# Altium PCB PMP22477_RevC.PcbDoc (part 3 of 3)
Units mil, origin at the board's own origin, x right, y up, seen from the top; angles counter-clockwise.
Board outline 5000 x 3000 mil, 4 copper layers (Top Layer, Signal Layer 1, Signal Layer 2, Bottom Layer), stack 61.2 mil thick; 191 components, 134 nets, 569 pads, 237 vias.
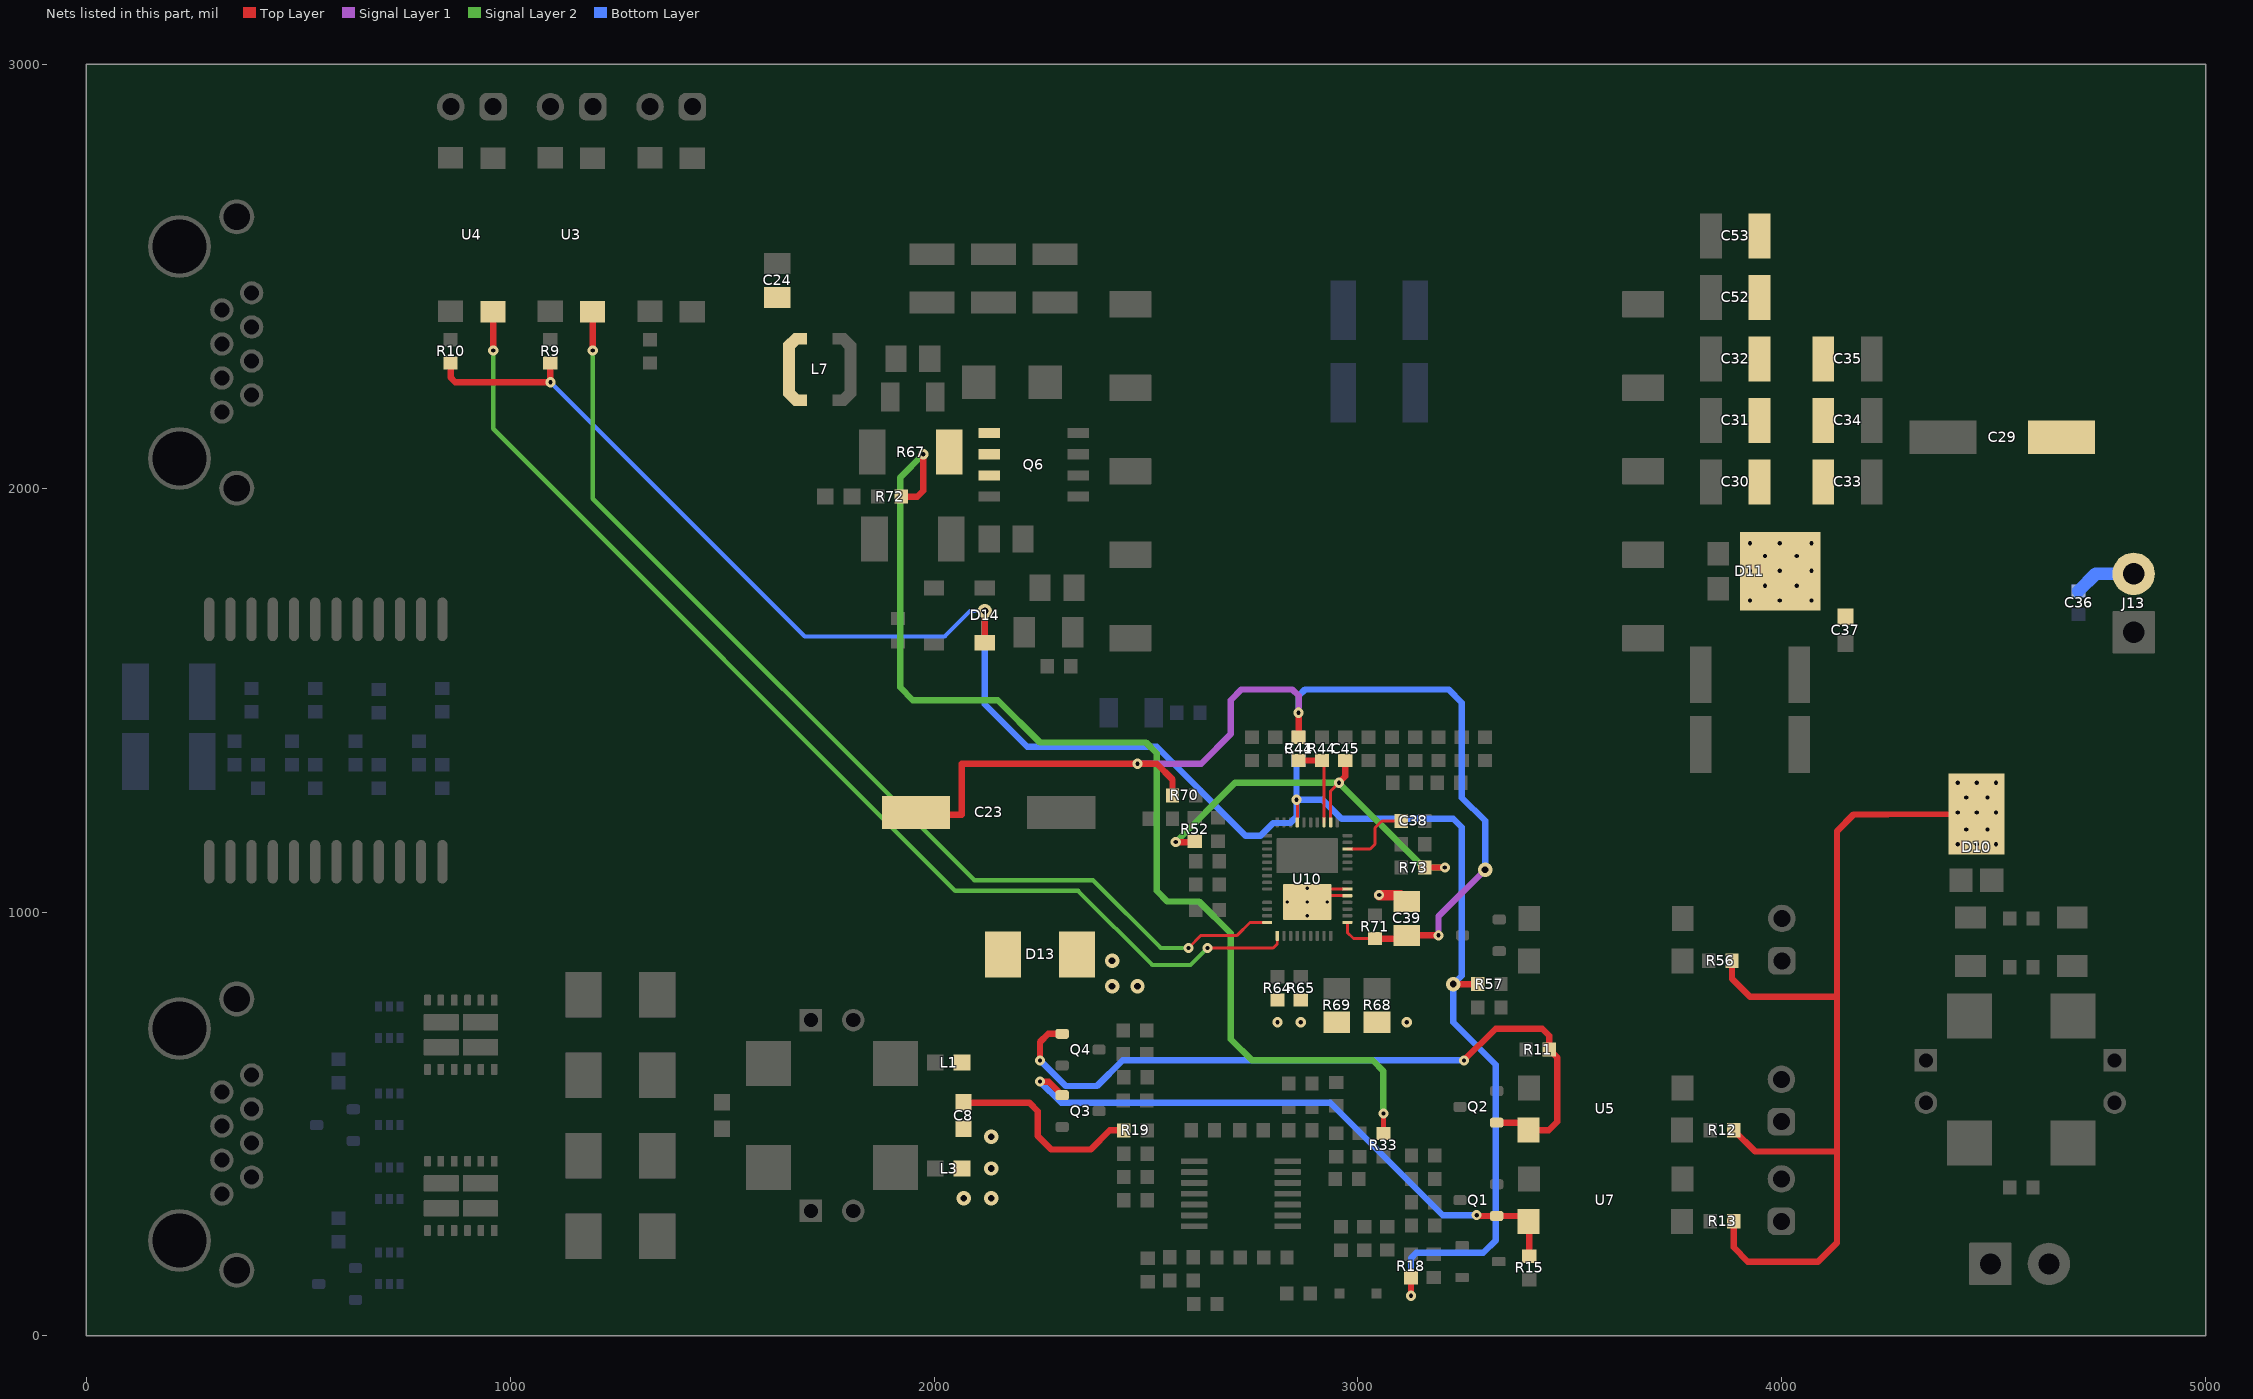
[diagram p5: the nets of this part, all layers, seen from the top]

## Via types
v1: diameter 34, hole 16, Top Layer to Bottom Layer, 127 vias
v2: diameter 24, hole 10, Top Layer to Bottom Layer, 97 vias
v3: diameter 19.68, hole 7.87, Top Layer to Bottom Layer, 13 vias

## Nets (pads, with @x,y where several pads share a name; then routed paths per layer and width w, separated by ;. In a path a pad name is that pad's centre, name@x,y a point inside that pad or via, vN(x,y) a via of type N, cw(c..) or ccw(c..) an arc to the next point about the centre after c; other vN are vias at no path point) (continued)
RSEN: Q6.1 Q6.2 Q6.3 R33.2 R67.1 R72.2 | length 2715.7
  Top Layer w12: R33.2@3060,477.56 v2(3060,525)
  Top Layer w15: R72.2@1922.56,1980 1960.59,1980 1974.69,1994.09 v2(1974.69,2080)
  Signal Layer 2 w15: v2(1974.69,2080) 1920,2025.31 1920,1530 1950,1500 2150,1500 2250,1400 2500,1400 2525,1375 2525,1050 2550,1025 2625,1025 2700,950 2700,700 2750,650 3035,650 3060,625 v2(3060,525)
SS: C38.1 U10.33 | length 177.6
  Top Layer w7: U10.33@2975,1148.74 3028.74,1148.74 3040,1160 3040,1198.7 3056.3,1215 C38.1@3102.44,1215
TPH: U3.2 U10.13 | length 2497.3
  Top Layer w7: v2(2600,915) 2630,945 2715,945 2745.51,975.51 U10.13@2786.02,975.51
  Top Layer w10: v2@1194.54,2325.46 v2(1195,2325)
  Top Layer w15: U3.2@1194.54,2416.32 1195,2415.86 v2(1195,2325)
  Signal Layer 2 w10: v2(1195,2325) 1195,1975 2095,1075 2375,1075 2535,915 v2(2600,915)
TPL: U4.2 U10.14 | length 2690.7
  Top Layer w7: v2(2645,915) 2800,915 2809.65,924.65 U10.14@2809.65,944.02
  Top Layer w10: v2@959.54,2325.46 v2(960,2325)
  Top Layer w15: U4.2@959.54,2416.32 960,2415.86 v2(960,2325)
  Signal Layer 2 w10: v2(960,2325) 960,2140 2050,1050 2340,1050 2515,875 2605,875 v2(2645,915)
TYPE1: Q2.1 Q4.1 R11.2 U5.4 | length 1762.7
  Top Layer w15: v2(2250,650) 2250,693.5 2269.36,712.86 Q4.1@2302.36,712.86 ; v2(3250,650) 3325,725 3435,725 3451.54,708.46 R11.2@3451.54,675.46 3470,656.99 3470,505 3450.46,485.46 U5.4@3402.38,485.46 3384.78,503.06 Q2.1@3327.28,503.06
  Bottom Layer w15: v2(2250,650) 2310.49,589.51 2384.51,589.51 2445,650 v2(3250,650)
TYPE2: Q1.1 Q3.1 R15.2 U7.4 | length 1437.7
  Top Layer w15: v2(2250,600) 2270.22,600 Q3.1@2302.36,567.86 ; v2(3280,285) 3281.94,283.06 Q1.1@3327.28,283.06 3389.78,283.06 U7.4@3402.38,270.46 3403.98,268.86 R15.2@3403.98,188.02
  Bottom Layer w15: v2(2250,600) 2300,550 2935,550 3200,285 v2(3280,285)
UV: R41.1 R44.2 U10.38 | length 202.7
  Top Layer w7: R44.2@2915,1357.44 2919.88,1352.56 U10.38@2919.88,1211.73
  Top Layer w15: R41.1@2860,1357.44 R44.2@2915,1357.44
VB: C45.1 R52.1 R73.1 U10.37 | length 1029.2
  Top Layer w7: U10.37@2935.63,1211.73 2935.63,1285.63 v2(2955,1305)
  Top Layer w15: v2(2570,1165) 2612.56,1165 R52.1@2615,1167.44 ; v2(2955,1305) 2970,1320 C45.1@2970,1357.44 ; R73.1@3157.56,1105 v2(3205,1105)
  Signal Layer 2 w15: v2(2570,1165) 2710,1305 v2(2955,1305) 3155,1105 v2(3205,1105)
VCC: C44.1 D14.1 R9.2 R10.2 R18.2 R57.1 U10.42 | length 4831.3
  Top Layer w7: v2(2855,1265) 2856.89,1263.11 U10.42@2856.89,1211.73
  Top Layer w15: R10.2@859.54,2295.35 859.54,2261.13 870.67,2250 v2(1095,2250) 1094.54,2250.46 R9.2@1094.54,2295.35 ; D14.1@2120,1635.53 v1(2120,1710) ; R18.2@3123.98,137.9 3125,136.87 v2(3125,95) ; v1(3225,830) R57.1@3282.44,830
  Bottom Layer w10: v2(1095,2250) 1695,1650 2025,1650 2085,1710 v1(2120,1710)
  Bottom Layer w15: v1(2120,1710) 2120,1490 2220,1390 2525,1390 2734.76,1180.24 2770.24,1180.24 2800,1210 2840,1210 2855,1225 v2(2855,1265) ; C44.1@2860,1357.44 2855,1352.44 v2(2855,1265) ; v2(3125,95) 3125,183.7 3137.31,196.01 3296.01,196.01 3325,225 3325,640 3225,740 v1(3225,830) 3245,850 3245,1200 3225,1220 2961.34,1220 2916.34,1265 v2(2855,1265)
VDD: C8.1 C23.1 C24.1 C39.1 D13.1 L1.2 L7.1 R19.2 R41.2 R70.2 R71.1 U10.23 | length 3169.4
  Top Layer w7: U10.23@2975,975.51 2975,951.81 2989.37,937.44 R71.1@3040,937.44
  Top Layer w15: C23.1@1957.48,1235 1962.6,1229.88 2065,1229.88 2065,1350 v2(2480,1350) 2525,1350 2562.44,1312.56 R70.2@2562.44,1275 ; C8.1@2069.43,551.5 2070.93,550 2225,550 2245,530 2245,471.65 2276.65,440 2369.88,440 2414.88,485 R19.2@2447.44,485 ; R41.2@2860,1412.56 v2(2860,1470) ; R71.1@3040,937.44 3107.44,937.44 C39.1@3115,945 v2(3190,945)
  Signal Layer 1 w15: v2(2480,1350) 2630,1350 2700,1420 2700,1500 2725,1525 2845,1525 2860,1510 v2(2860,1470) ; v2(3190,945) 3190,990 v1(3300,1100)
  Bottom Layer w15: v2(2860,1470) 2860,1510 2875,1525 3213.85,1525 3245,1493.85 3245,1270 3300,1215 v1(3300,1100)
VOUT: C29.1 C30.2 C31.2 C32.2 C33.2 C34.2 C35.2 C36.1 C37.1 C52.2 C53.2 D10.3 D11.3 J13.2 R12.1 R13.1 R56.1 | length 2372
  Top Layer w15: R56.1@3882.56,885 3882.56,842.44 3925,800 4130,800 ; R13.1@3886.54,270.46 3886.54,208.92 3920,175.46 4085.46,175.46 4130,220 4130,435 ; R12.1@3886.54,485.46 3936.99,435 4130,435 ; D10.3@4458.78,1231.77 4415.03,1231.4 4250,1230 4168.98,1230 4130,1191.02 4130,800 ; 4130,435 4130,800
  Bottom Layer w30: C36.1@4700,1757.56 4740.44,1798 J13.2@4830,1798
  other v2: 4415,1160 4460,1160 4505,1160 4435,1195 4485,1195 4415,1235 4460,1235 4505,1235 4435,1270 4485,1270 4415,1305 4460,1305 4505,1305 3925,1735 3995,1735 4070,1735 3960,1770 4035,1770 3925,1805 3995,1805 4070,1805 3960,1840 4035,1840 3925,1870 3995,1870 4070,1870
VSS: C8.2 C39.2 D13.2 L3.2 R64.1 R65.1 R68.1 R69.1 U10.27 U10.28 U10.47 | length 258.1
  Top Layer w7: v3(2880.51,1023.74) U10.47@2895.28,1038.5 ; U10.27@2975,1038.5 U10.47@2895.28,1038.5 ; U10.28@2975,1054.25 2911.02,1054.25 U10.47@2895.28,1038.5
  Top Layer w25: v2(3050,1040) 3100,1040 C39.2@3115,1025
  other v1: 2070,325 2135,325 2135,395 2135,470 2420,825 2480,825 2420,885
  other v2: 2810,740 2865,740 3115,740
  other v3: 2880.51,991.26 2833.27,1023.74 2927.76,1023.74 2880.51,1056.22
pads on no net: D17.3 D18.3 T2.2 T2.8 U9.3 U10.6 U10.10 U10.15 U10.16 U10.22 U10.25 U10.26 U10.29 U10.30 U10.41

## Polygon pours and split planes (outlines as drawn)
PGND on Top Layer "TOP_LAYER_PGND_P102" (solid, remove dead copper, pour order 102): 800,2650 2995,2650 2995,1550 3350,1550 3350,1100 3550,1100 3550,50 2045,50 2045,850 1550,850 1550,1400 800,2150
no net on Top Layer "TOP_LAYER_NONET_P086" (solid, remove dead copper, pour order 86): 2817.52,694.16
VSS on Top Layer "TOP_LAYER_VSS_P084" (solid, remove dead copper, pour order 84): 2600,700 2600,750 2550,800 2295,800 2295,1000 2450,1000 2582.76,867.24 2631.34,867.24 2631.34,868.66 2630,870 2765,870 2765,810 2885,810 2885,765 3150,765 3150,700
GND on Top Layer "TOP_LAYER_GND_P088" (solid, remove dead copper, pour order 88): 3650,50 3650,1200 3450,1200 3450,1650 3100,1650 3100,2750 800,2750 800,2950 4950,2950 4950,960 4250,960 4250,50
VSS on Top Layer "TOP_LAYER_VSS_P060" (solid, remove dead copper, pour order 60): 2200,250 2200,505 2045,505 2045,250
NetJ4_2 on Top Layer "TOP_LAYER_NETJ4_2_P056" (solid, remove dead copper, pour order 56): 1780,265 2020,265 2020,455 1855,455 1855,325 1780,325
NetJ3_2 on Top Layer "TOP_LAYER_NETJ3_2_P054" (solid, remove dead copper, pour order 54): 1780,775 2020,775 2020,585 1855,585 1855,715 1780,715
NetC15_1 on Top Layer "TOP_LAYER_NETC15_1_P052" (solid, remove dead copper, pour order 52): 4300,1105 4550,1105 4550,960 4300,960
NetC19_1 on Top Layer "TOP_LAYER_NETC19_1_P050" (solid, remove dead copper, pour order 50): 4825,620 4825,900 4575,900 4575,810 4630,810 4630,700 4740,700 4740,620
NetC19_2 on Top Layer "TOP_LAYER_NETC19_2_P048" (solid, remove dead copper, pour order 48): 4550,900 4550,810 4500,810 4500,700 4390,700 4390,620 4300,620 4300,900
NetC20_1 on Top Layer "TOP_LAYER_NETC20_1_P044" (solid, remove dead copper, pour order 44): 4575,100 4575,400 4630,400 4630,510 4740,510 4740,580 4825,580 4825,100
NetC20_2 on Top Layer "TOP_LAYER_NETC20_2_P042" (solid, remove dead copper, pour order 42): 4550,100 4550,400 4500,400 4500,510 4390,510 4390,580 4300,580 4300,100
NetD11_1 on Top Layer "TOP_LAYER_NETD11_1_P040" (solid, remove dead copper, pour order 40): 3875,1900 3875,1315 3615,1315 3615,1900
NetC37_2 on Top Layer "TOP_LAYER_NETC37_2_P038" (solid, remove dead copper, pour order 38): 4170,1645 4170,1315 3900,1315 3900,1645
VOUT on Top Layer "TOP_LAYER_VOUT_P036" (solid, remove dead copper, pour order 36): 4550,1900 4300,1900 4300,1135 4725,1135 4725,1740 4950,1740 4950,2700 3900,2700 3900,1675 4250,1675 4250,1900 4140,1900 4140,2400 4550,2400
RSEN on Top Layer "TOP_LAYER_RSEN_P034" (solid, remove dead copper, pour order 34): 2155,2145 2155,2020 1950,2020 1950,2145
VDD on Top Layer "TOP_LAYER_VDD_P032" (solid, remove dead copper, pour order 32): 2100,1390 2025,1465 1844.3,1464.3 1700,1608.61 1700,2475 1500,2475 1500,1450.31 1550,1400.31 1550,850 2045,850 2045,535 2200,535 2200,750 2250,800 2250,1100 2100,1100
NetC22_2 on Top Layer "TOP_LAYER_NETC22_2_P030" (solid, remove dead copper, pour order 30): 2065,2365 2065,2340 2415,2340 2415,2300 2625,2300 2625,2475 1760,2475 1760,2175 1935,2175 1935,2365
NetC49_2 on Top Layer "TOP_LAYER_NETC49_2_P028" (solid, remove dead copper, pour order 28): 2520,1925 2380,1925 2380,1830 2185,1830 2185,1950 2185,2160 2185,2315 2380,2315 2380,2150 2520,2150
BSP on Top Layer "TOP_LAYER_BSP_P104" (solid, remove dead copper, pour order 104): 700,2940 700,2600 400,2600 400,250 450,250 450,60 60,60 60,2940
NetC7_2 on Top Layer "TOP_LAYER_NETC7_2_P024" (solid, remove dead copper, pour order 24): 1530,505 1530,455 1665,455 1665,325 1740,325 1740,265 1470,265 1470,505
NetC7_1 on Top Layer "TOP_LAYER_NETC7_1_P022" (solid, remove dead copper, pour order 22): 1530,535 1530,585 1665,585 1665,715 1740,715 1740,775 1305,775 1305,535
NetC7_1 on Top Layer "TOP_LAYER_NETC7_1_P020" (solid, remove dead copper, pour order 20): 1425,155 1425,1050 1280,1050 1280,155
PR12 on Top Layer "TOP_LAYER_PR12_P006" (solid, remove dead copper, pour order 6): 1050,725 1050,885 1235,885 1235,725
PR36 on Top Layer "TOP_LAYER_PR36_P004" (solid, remove dead copper, pour order 4): 1235,535 1235,695 1050,695 1050,535
PR45 on Top Layer "TOP_LAYER_PR45_P002" (solid, remove dead copper, pour order 2): 1235,345 1235,505 1050,505 1050,345
PR78 on Top Layer "TOP_LAYER_PR78_P000" (solid, remove dead copper, pour order 0): 1235,155 1235,315 1050,315 1050,155
PGND on Bottom Layer "BOTTOM_LAYER_PGND_P100" (solid, remove dead copper, pour order 100): 2045,50 2045,850 1550,850 1550,1400 800,2150 800,2650 2995,2650 2995,1550 3350,1550 3350,1100 3550,1100 3550,50
GND on Bottom Layer "BOTTOM_LAYER_GND_P094" (solid, remove dead copper, pour order 94): 4250,50 4250,960 4950,960 4950,2950 800,2950 800,2750 3100,2750 3100,1650 3450,1650 3450,1200 3650,1200 3650,50
NetC37_2 on Bottom Layer "BOTTOM_LAYER_NETC37_2_P078" (solid, remove dead copper, pour order 78): 4170,1315 3900,1315 3900,1645 4170,1645
NetD11_1 on Bottom Layer "BOTTOM_LAYER_NETD11_1_P072" (solid, remove dead copper, pour order 72): 3615,1315 3615,1900 3875,1900 3875,1315
NetC22_2 on Bottom Layer "BOTTOM_LAYER_NETC22_2_P062" (solid, remove dead copper, pour order 62): 2995,2490 2995,2350 2550,2350 2550,2490
VSS on Bottom Layer "BOTTOM_LAYER_VSS_P026" (solid, remove dead copper, pour order 26): 2200,700 2650,700 3150,700 3150,1065 2825,1065 2825,870 2580,870 2500,950 2450,1000 2045,1000 2045,250 2200,250
BSP on Bottom Layer "BOTTOM_LAYER_BSP_P106" (solid, remove dead copper, pour order 106): 700,2940 700,2600 400,2600 400,250 450,250 450,60 60,60 60,2940
NetC7_2 on Bottom Layer "BOTTOM_LAYER_NETC7_2_P016" (solid, remove dead copper, pour order 16): 1280,50 1425,50 1425,265 1530,265 1530,505 1425,505 1425,885 1280,885
PR78 on Bottom Layer "BOTTOM_LAYER_PR78_P014" (solid, remove dead copper, pour order 14): 1050,155 1233.5,155 1235,156.5 1235,315 1050,315
PR45 on Bottom Layer "BOTTOM_LAYER_PR45_P012" (solid, remove dead copper, pour order 12): 1050,345 1235,345 1235,505 1050,505
PR36 on Bottom Layer "BOTTOM_LAYER_PR36_P010" (solid, remove dead copper, pour order 10): 1050,695 1235,695 1235,535 1050,535
PR12 on Bottom Layer "BOTTOM_LAYER_PR12_P008" (solid, remove dead copper, pour order 8): 1050,885 1235,885 1235,725 1050,725
NetC7_2 on Signal Layer 2 "SIGNAL_LAYER_2_NETC7_2_P108" (solid, remove dead copper, pour order 108): 890,900 890,50 1425,50 1425,150 975,150 975,900
PGND on Signal Layer 2 "SIGNAL_LAYER_2_PGND_P098" (solid, remove dead copper, pour order 98): 2045,50 3550,50 3550,1100 3350,1100 3350,1550 2995,1550 2995,2650 800,2650 800,2150 1550,1400 1550,850 2045,850
VSS on Signal Layer 2 "SIGNAL_LAYER_2_VSS_P082" (solid, remove dead copper, pour order 82): 2775,700 3150,700 3150,1065 2825,1065 2825,870 2775,870
GND on Signal Layer 2 "SIGNAL_LAYER_2_GND_P092" (solid, remove dead copper, pour order 92): 4250,50 4250,960 4950,960 4950,2950 800,2950 800,2750 3100,2750 3100,1650 3450,1650 3450,1200 3650,1200 3650,50
NetC37_2 on Signal Layer 2 "SIGNAL_LAYER_2_NETC37_2_P076" (solid, remove dead copper, pour order 76): 3900,1315 3900,1645 4170,1645 4170,1315
NetD11_1 on Signal Layer 2 "SIGNAL_LAYER_2_NETD11_1_P068" (solid, remove dead copper, pour order 68): 3615,1315 3615,1900 3875,1900 3875,1315
VOUT on Signal Layer 2 "SIGNAL_LAYER_2_VOUT_P064" (solid, remove dead copper, pour order 64): 4550,1900 4300,1900 4300,1135 4725,1135 4725,1740 4950,1740 4950,2700 3900,2700 3900,1675 4250,1675 4250,1900 4140,1900 4140,2400 4550,2400
NetC7_1 on Signal Layer 2 "SIGNAL_LAYER_2_NETC7_1_P018" (solid, remove dead copper, pour order 18): 1425,885 1290,885 1290,950 865,950 865,155 780,155 780,1050 1425,1050
PGND on Signal Layer 1 "SIGNAL_LAYER_1_PGND_P096" (solid, remove dead copper, pour order 96): 2995,2650 800,2650 800,2150 1550,1400 1550,850 2045,850 2045,50 3550,50 3550,1100 3350,1100 3350,1550 2995,1550
VSS on Signal Layer 1 "SIGNAL_LAYER_1_VSS_P080" (solid, remove dead copper, pour order 80): 3150,1065 2825,1065 2825,870 2775,870 2775,700 3150,700
GND on Signal Layer 1 "SIGNAL_LAYER_1_GND_P090" (solid, remove dead copper, pour order 90): 4250,50 4250,960 4950,960 4950,2950 800,2950 800,2750 3100,2750 3100,1650 3450,1650 3450,1200 3650,1200 3650,50
NetC37_2 on Signal Layer 1 "SIGNAL_LAYER_1_NETC37_2_P074" (solid, remove dead copper, pour order 74): 4170,1315 3900,1315 3900,1645 4170,1645
NetD11_1 on Signal Layer 1 "SIGNAL_LAYER_1_NETD11_1_P066" (solid, remove dead copper, pour order 66): 3615,1315 3875,1315 3875,1900 3615,1900

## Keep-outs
Keep-Out Layer:
  text ".Layer_Name" at 577,-858.49 h60

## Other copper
Top Layer:
  text ".Layer_Name" at 577,-858.49 h60
Bottom Layer:
  text ".Layer_Name" at 577,-858.49 h60

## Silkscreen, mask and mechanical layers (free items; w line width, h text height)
Top Overlay:
  text "'.PRJ_Number'.PCB_Rev" at 4265,2725 h108.27
  text ".Layer_Name" at 577,-858.49 h60
Bottom Overlay:
  text ".Layer_Name" at 577,-858.49 h60
Top Paste:
  text ".Layer_Name" at 577,-858.49 h60
Bottom Paste:
  text ".Layer_Name" at 577,-858.49 h60
Top Solder:
  text ".Layer_Name" at 577,-858.49 h60
  text ".Layer_Name" at 577,-858.49 h60
Bottom Solder:
  text ".Layer_Name" at 577,-858.49 h60
Drill Guide:
  text ".Layer_Name" at 577,-858.49 h60
M1 Board Outline:
  the board outline again, w10
  text ".Layer_Name" at 577,-858.49 h60
M2 Board Dimensions:
  rectangle: 0,-275 125,-150
  rectangle: 125,-400 500,-275
  lines w7: 0,-275 1000,-275 ; 125,-400 125,-150 ; 250,-400 250,-150 ; 500,-400 500,-150 ; 750,-400 750,-150 ; 0,-400 1000,-400 1000,-150 0,-150 0,-400
  text ".Layer_Name" at 577,-858.49 h60
M3 3D STEP Top:
  text ".Layer_Name" at 577,-858.49 h60
M4 3D STEP Bottom:
  text ".Layer_Name" at 577,-858.49 h60
M5 Assembly Top:
  lines w10: -292,-930.17 6308,-930.17 ; -292,-726.83 6310,-726.83 ; -292,-523.5 -292,-1133.5 3713,-1133.5 6310,-1133.5 6310,-523.5 -291.5,-523.5 -291.5,-1133.5 1284,-1133.5 ; 2173,-1133.5 2173,-523.5 ; 3440,-726.83 3440,-523.5 ; 4280,-726.83 4280,-523.5 ; 4902,-1140 4902,-937.17
  text "COMPONENTS MARKED 'DNP' SHOULD NOT BE POPULATED." at 1153.5,-318.5 h60
  text "ASSEMBLY VARIANT:" at 1153,-434 h60
  text ".VariantName" at 2189,-434 h60
  text "PCB VIEWED FROM TOP SIDE" at -228.5,-655.67 h60
  text "BOARD #:" at 2248,-655.67 h60
  text ".PRJ_Number" at 2793.5,-655.67 h60
  text "REV:" at 3638,-655.67 h60
  text ".PCB_Rev" at 3929.5,-655.67 h60
  text "SVN REV:" at 4476,-655.67 h60
  text ".VersionControl_RevNumber" at 4982,-655.67 h60
  text "TID #:" at 2248,-859 h60
  text ".TID" at 2793.5,-859 h60
  text "PLOT NAME =" at -228.5,-1064.34 h60
  text ".plot_File_Name" at 577,-1064.34 h60
  text "GENERATED    :" at 2250,-1064.34 h60
  text ".Print_Date" at 3119.5,-1064.34 h60
  text ".Print_Time" at 3848.5,-1064.34 h60
  text "TEXAS INSTRUMENTS" at 5113,-1064.34 h60
M6 Assembly Bottom:
  lines w10: -292.5,-727.33 6309.5,-727.33 ; -290.5,-930.67 6309.5,-930.67 ; 1115.5,-1140.5 1115.5,-937.67 ; 1737.5,-727.33 1737.5,-524 ; 2577.5,-727.33 2577.5,-524 ; 3844.5,-1134 3844.5,-524 ; 4733.5,-1134 6309,-1134 6309,-524 -292.5,-524 -292.5,-1134 2304.5,-1134 6309.5,-1134 6309.5,-524
  text "COMPONENTS MARKED 'DNP' SHOULD NOT BE POPULATED." at 6102,-318 h60
  text ".VariantName" at 5058,-434 h60
  text "ASSEMBLY VARIANT:" at 6097,-434 h60
  text ".VersionControl_RevNumber" at 1035.5,-656.17 h60
  text "SVN REV:" at 1541.5,-656.17 h60
  text ".PCB_Rev" at 2088,-656.17 h60
  text "REV:" at 2379.5,-656.17 h60
  text ".PRJ_Number" at 3224,-656.17 h60
  text "BOARD #:" at 3769.5,-656.17 h60
  text "PCB VIEWED FROM BOTTOM SIDE" at 6246,-656.17 h60
  text ".TID" at 3224,-859.5 h60
  text "TID #:" at 3769.5,-859.5 h60
  text "TEXAS INSTRUMENTS" at 904.5,-1064.84 h60
  text ".Print_Time" at 2169,-1064.84 h60
  text ".Print_Date" at 2898,-1064.84 h60
  text "GENERATED    :" at 3767.5,-1064.84 h60
  text ".plot_File_Name" at 5440.5,-1064.84 h60
  text "PLOT NAME =" at 6246,-1064.84 h60
M9 Title Sheet:
  drawing of 57 lines, arcs and shapes, not listed
  text "1" at 739.84,8036.5 h70
  text "2" at 3235.5,8036.5 h70
  text "3" at 5724.84,8036.5 h70
  text "4" at 8231.51,8036.5 h70
  text "5" at 10730.5,8036.5 h70
  text "6" at 13235.5,8036.5 h70
  text "A" at -416.5,6893.5 h70
  text "A" at 14383.5,6893.5 h70
  text "B" at -416.5,4513.5 h70
  text "B" at 14383.5,4513.5 h70
  text "C" at -416.5,2138.5 h70
  text "C" at 14383.5,2138.5 h70
  text "PROJECT TITLE:" at 11343.5,277.5 h45
  text ".PRJ_Title" at 11393.5,144.17 h70
  text "DESIGNED FOR:" at 11343.5,-23.5 h45
  text ".PRJ_Customer" at 11393.5,-163.5 h70
  text "D" at -416.5,-231.5 h70
  text "D" at 14383.5,-231.5 h70
  text "FILE NAME:" at 11343.5,-323.5 h45
  text ".PCB_File_Name_No_Path" at 11393.5,-443.5 h70
  text "Texas Instruments (TI) and/or its licensors do not warrant the accuracy or completeness of this specification" at 6374,-605.34 h45
  text "ENGINEER:" at 11343.5,-613.5 h45
  text "LAYOUT BY:" at 12848.5,-613.5 h45
  text "or any information contained therein. TI and/or its licensors do not warrant that this design will meet" at 6329.01,-718 h45
  text ".PRJ_Engineer" at 11393.5,-768.49 h70
  text ".PCB_Layout" at 12899,-768.49 h70
  text "the specifications, will be suitable for your application or fit for any particular purpose, or will operate in" at 6329.01,-830.67 h45
  text ".Layer_Name" at 577,-858.49 h60
  text "ALTIUM DESIGNER VERSION:" at 12848.5,-923.5 h45
  text "an implementation. TI and/or its licensors do not warrant that the design is production worthy. You should" at 6329.01,-943.33 h45
  text "completely validate and test your design implementation to confirm the system functionality for your application." at 6374,-1056 h45
  text ".print_Scale" at 11393.5,-1056.83 h70
  text ".Application_BuildNumber" at 12899,-1056.83 h70
  text "1" at 739.84,-1263.5 h70
  text "2" at 3235.5,-1263.5 h70
  text "3" at 5724.84,-1263.5 h70
  text "4" at 8231.51,-1263.5 h70
  text "5" at 10730.5,-1263.5 h70
  text "6" at 13235.5,-1263.5 h70
M10 Fab Notes:
  drawing of 189 lines, arcs and shapes, not listed
  text "DESIGN INFORMATION" at 12382.02,6356.17 h60
  text "MIN. TRACK WIDTH:" at 11737.46,6224.05 h60
  text "8" at 12833.7,6224.05 h60
  text "MIL" at 12988.46,6224.05 h60
  text "MIN. CLEARANCE:" at 11737.46,6099.92 h60
  text "0.2" at 12773.7,6099.93 h60
  text "mm" at 12988.46,6099.92 h60
  text "MIN. VIA PAD SIZE:" at 11737.46,5975.8 h60
  text "24" at 12803.71,5975.8 h60
  text "MIL" at 12988.46,5975.8 h60
  text "0.05mm (2MIL)" at 12432.46,5845.9 h60
  text "MINIMUM ANNULAR RING" at 11408.23,5837.67 h60
  text "EXTERNAL" at 13140.46,5837.67 h60
  text "PER" at 11608.23,5727.55 h60
  text "IPC-D-275 CLASS 2 LEVEL C" at 11828.23,5727.54 h60
  text "MIL, HOLES" at 13316.46,5627.07 h60
  text "+/-" at 12924,5618.48 h60
  text "+/-" at 13778,5618.48 h60
  text "REGISTRATION TOLERANCES:" at 11408.23,5617.42 h60
  text "METAL" at 12608,5617.42 h60
  text "5" at 13184.2,5617.42 h60
  text "3" at 14017.2,5617.42 h60
  text "MIL" at 14133.46,5617.42 h60
  text "HOLE SIZE TOLERANCE (UNLESS OTHERWISE SPECIFIED):" at 11408.23,5519.1 h60
  text "+/-" at 13778,5516.23 h60
  text "3" at 14017.2,5515.17 h60
  text "MIL" at 14133.46,5515.17 h60
  text "MATERIAL:" at 11333.46,5377.52 h60
  text "FR-4 High Tg" at 12319.9,5249 h60
  text "X" at 12175.46,5241.01 h60
  text "FR-408" at 11754.46,5236.49 h60
  text "OTHER" at 13242.46,5236.49 h60
  text "62 MIL (1.6mm) +/-10%" at 12074.56,5093.46 h60
  text "X" at 11954.46,5091.01 h60
  text "THICKNESS:" at 11408.23,5085.24 h60
  text "OTHER" at 13359.46,5085.24 h60
  text "TOLERANCE:" at 11408.23,4946.92 h60
  text "X" at 12256.46,4946.92 h60
  text "ANSI IPC-6012 TYPE 3 CLASS 2" at 12434.48,4946.92 h60
  text "OTHER +/-" at 12434.46,4802.73 h60
  text "BOW & TWIST:" at 11408.23,4657.54 h60
  text "X" at 12256.46,4657.54 h60
  text "ANSI IPC-6012 TYPE 3 CLASS 2" at 12434.48,4657.54 h60
  text "OTHER +/-" at 12434.46,4510.85 h60
  text "DRILLING:" at 11333.46,4380.23 h60
  text "NC_DRILL FILES" at 13094.46,4275.04 h60
  text "REFERENCE:" at 11408.23,4271.1 h60
  text "X" at 12065.46,4271.01 h60
  text "AS SHOWN" at 12243.46,4271.1 h60
  text "X" at 12966.46,4271.1 h60
  text "OTHER" at 13392.46,4128.85 h60
  text "PTH COPPER THICKNESS:" at 11407.91,4125.32 h60
  text "X" at 12547.14,4125.32 h60
  text "20-30 um" at 12675.14,4125.32 h60
  text "BOARD FINISH:" at 11333.46,3977.73 h60
  text "SILKSCREEN:" at 11488.68,3867.6 h60
  text "X" at 12446.46,3867.6 h60
  text "TOP" at 12563.46,3867.6 h60
  text "X" at 12956.46,3867.6 h60
  text "BOTTOM" at 13074.46,3867.6 h60
  text "SILKSCREEN COLOR:" at 11488.68,3712.41 h60
  text "X" at 12445.46,3712.41 h60
  text "WHITE" at 12563.46,3712.41 h60
  text "OTHER" at 13074.46,3712.41 h60
  text "X" at 12576.46,3568.96 h60
  text "GREEN" at 12694.46,3568.96 h60
  text "OTHER" at 13312.46,3568.96 h60
  text "SOLDER RESIST COLOR:" at 11488.68,3562.1 h60
  text "X" at 12576.46,3414.71 h60
  text "MATTE" at 12694.46,3414.71 h60
  text "SEMI-GLOSS" at 13312,3414.07 h60
  text "IMMERSION GOLD (ENIG)" at 12394.46,3241.94 h60
  text "ENEPIG" at 13732,3234.72 h60
  text "SURFACE FINISH:" at 11333.46,3233.72 h60
  text "X" at 12216.46,3233.72 h60
  text "IMM. TIN/SILVER OR EQUIV" at 11663,3096.4 h60
  text "OTHER" at 13094.46,3092.47 h60
  text "ARRAY/PANEL:" at 11333.46,2937.09 h60
  text "X" at 12216.46,2930 h60
  text "CUT AND TRIM PER M1 BOARD OUTLINE" at 12394.46,2928.87 h60
  text "N.C. ROUTE" at 12394.46,2792.9 h60
  text "V. SCORE" at 13260.46,2792.9 h60
  text "CERTIFICATION:" at 11333.46,2663.77 h60
  text "MATERIALS AND WORKMANSHIP FOR ALL PCBS" at 12058.46,2663.77 h60
  text "TO MEET OR EXCEED THE REQUIREMENTS OF:" at 12058.46,2569.71 h60
  text "X" at 11695.97,2441.08 h60
  text "ANSI IPC-A-600F CLASS ->" at 11823.96,2441.08 h60
  text "X" at 13471.97,2441.08 h60
  text "2" at 13581.96,2441.08 h60
  text "1" at 13266.96,2439.58 h60
  text "3" at 13935.96,2439.58 h60
  text "X" at 12507.97,2293.39 h60
  text "RoHS" at 12635.96,2293.39 h60
  text "OTHER" at 13280.36,2293.39 h60
  text "PER ORDER" at 13677.42,2293.39 h60
  text "ALL BOARDS MUST MEET OR EXCEED UL94-V0 REQUIREMENTS." at 11361,2139.57 h60
  text "PCB MUST BEAR THE UL94V-0 UL REGISTERED MATERIAL ID NUMBER" at 11361,2023.5 h60
  text "ADDITIONAL REQUIREMENTS:" at 11333.46,1854.08 h60
  text "MICROSECTION:" at 11408.23,1746.95 h60
  text "YES" at 12313.96,1746.95 h60
  text "REQUIRED" at 13175.46,1602.62 h60
  text "BARE BOARD ELEC. TEST:" at 11408.23,1599.76 h60
  text "NONE" at 12713.96,1599.76 h60
  text "X" at 13057.46,1599.76 h60
  text "PER ORDER" at 13767.46,1599.76 h60
  text "XX MIL VIAS REQUIRE NON-CONDUCTIVE FILL AND PLANARIZE" at 11576.38,1394.82 h59
  text "XX MIL VIAS REQUIRE CONDUCTIVE FILL AND PLANARIZE" at 11584.38,1290.84 h60
  text "OUTER XX MIL TRACES REQUIRE 50 OHM SINGLE-ENDED IMPEDANCE" at 11583.39,1127.46 h58
  text "LAYER 2 & 3 (INNER LAYERS) XX MIL WIDE, XX MIL SPACE / TRACES REQUIRE 100 OHM DIFFERENTIAL IMPEDANCE" at 11575.39,891.74 h60
  text ".Layer_Name" at 577,-858.49 h60
M11 Gerber Information:
  lines w10: -292,-930.17 6308,-930.17 ; -292,-726.83 6310,-726.83 ; -292,-523.5 -292,-1133.5 3713,-1133.5 6310,-1133.5 6310,-523.5 -291.5,-523.5 -291.5,-1133.5 1284,-1133.5 ; 2173,-1133.5 2173,-523.5 ; 3440,-726.83 3440,-523.5 ; 4280,-726.83 4280,-523.5 ; 4902,-1140 4902,-937.17
  text "ALL ARTWORK VIEWED FROM TOP SIDE" at -228.5,-655.67 h60
  text "BOARD #:" at 2248,-655.67 h60
  text ".PRJ_Number" at 2793.5,-655.67 h60
  text "REV:" at 3638,-655.67 h60
  text ".PCB_Rev" at 3929.5,-655.67 h60
  text "SVN REV:" at 4476,-655.67 h60
  text ".VersionControl_RevNumber" at 4982,-655.67 h60
  text "LAYER NAME =" at -228.5,-858.49 h60
  text "TID #:" at 2248,-859 h60
  text ".TID" at 2793.5,-859 h60
  text "PLOT NAME =" at -228.5,-1064.34 h60
  text ".plot_File_Name" at 577,-1064.34 h60
  text "GENERATED    :" at 2250,-1064.34 h60
  text ".Print_Date" at 3119.5,-1064.34 h60
  text ".Print_Time" at 3848.5,-1064.34 h60
  text "TEXAS INSTRUMENTS" at 5113,-1064.34 h60
M12 Stackup:
  drawing of 295 lines, arcs and shapes, not listed
  text "Layer" at 9736.2,7835 h60
  text "Name" at 10146.11,7835 h60
  text "Material" at 11085.85,7835 h60
  text "Thickness" at 11945.62,7835 h60
  text "Constant" at 12595.46,7835 h60
  text "Board Layer Stack" at 13165.32,7835 h60
  text "1" at 9736.2,7715 h60
  text "Top Overlay" at 10146.11,7715 h60
  text "2" at 9736.2,7595 h60
  text "Top Solder" at 10146.11,7595 h60
  text "Solder Resist" at 11085.85,7595 h60
  text "0.40mil" at 11945.62,7595 h60
  text "3.5" at 12595.46,7595 h60
  text "3" at 9736.2,7475 h60
  text "Top Layer" at 10146.11,7475 h60
  text "Copper" at 11085.85,7475 h60
  text "2.80mil" at 11945.62,7475 h60
  text "4" at 9736.2,7355 h60
  text "Dielectric1" at 10146.11,7355 h60
  text "FR-4" at 11085.85,7355 h60
  text "15.00mil" at 11945.62,7355 h60
  text "4.8" at 12595.46,7355 h60
  text "5" at 9736.2,7235 h60
  text "Signal Layer 1" at 10146.11,7235 h60
  text "Copper" at 11085.85,7235 h60
  text "2.80mil" at 11945.62,7235 h60
  text "6" at 9736.2,7115 h60
  text "Dielectric 2" at 10146.11,7115 h60
  text "20.00mil" at 11945.62,7115 h60
  text "4.2" at 12595.46,7115 h60
  text "7" at 9736.2,6995 h60
  text "Signal Layer 2" at 10146.11,6995 h60
  text "Copper" at 11085.85,6995 h60
  text "2.80mil" at 11945.62,6995 h60
  text "8" at 9736.2,6875 h60
  text "Dielectric 3" at 10146.11,6875 h60
  text "15.00mil" at 11945.62,6875 h60
  text "4.2" at 12595.46,6875 h60
  text "9" at 9736.2,6755 h60
  text "Bottom Layer" at 10146.11,6755 h60
  text "Copper" at 11085.85,6755 h60
  text "2.80mil" at 11945.62,6755 h60
  text "10" at 9736.2,6635 h60
  text "Bottom Solder" at 10146.11,6635 h60
  text "Solder Resist" at 11085.85,6635 h60
  text "0.40mil" at 11945.62,6635 h60
  text "3.5" at 12595.46,6635 h60
  text "11" at 9736.2,6515 h60
  text "Bottom Overlay" at 10146.11,6515 h60
  text ".Layer_Name" at 577,-858.49 h60
M13 Component Bodies Top:
  text ".Layer_Name" at 577,-858.49 h60
M14 Component Bodies Bottom:
  text ".Layer_Name" at 577,-858.49 h60
M15 Courtyards Top:
  text ".Layer_Name" at 577,-858.49 h60
M16 Courtyards Bottom:
  text ".Layer_Name" at 577,-858.49 h60
Drill Drawing:
  circle w10: c5343.54,994.66 r27.56
  lines w10: 5315.98,236.72 5329.76,236.72 5329.76,222.94 5357.32,222.94 5357.32,236.72 5371.1,236.72 5371.1,264.28 5357.32,264.28 5357.32,278.06 5329.76,278.06 5329.76,264.28 5315.98,264.28 5315.98,236.72 ; 5315.98,346.97 5343.54,360.75 5371.1,346.97 5357.32,374.53 5371.1,402.09 5343.54,388.31 5315.98,402.09 5329.76,374.53 5315.98,346.97 ; 5315.98,526.12 5371.1,526.12 5343.54,470.99 5315.98,526.12 ; 5315.98,608.8 5329.76,608.8 5343.54,595.02 5357.32,608.8 5371.1,608.8 5357.32,622.58 5371.1,636.36 5357.32,636.36 5343.54,650.14 5329.76,636.36 5315.98,636.36 5329.76,622.58 5315.98,608.8 ; 5315.98,719.05 5315.98,732.83 5329.76,746.61 5315.98,760.39 5315.98,774.17 5329.76,774.17 5343.54,760.39 5357.32,774.17 5371.1,774.17 5371.1,760.39 5357.32,746.61 5371.1,732.83 5371.1,719.05 5357.32,719.05 5343.54,732.83 5329.76,719.05 5315.98,719.05 ; 5315.98,843.07 5371.1,843.07 5371.1,898.2 5315.98,898.2 5315.98,843.07 ; 5315.98,1091.13 5371.1,1091.13 5371.1,1146.25 5315.98,1146.25 5315.98,1091.13 ; 5315.98,1242.72 5343.54,1215.15 5371.1,1242.72 5343.54,1270.28 5315.98,1242.72 ; 5327,1102.15 5360.08,1102.15 5360.08,1135.23 5327,1135.23 5327,1102.15
  lines w12: 5266,185.73 8492.8,185.73 ; 5266,1301.97 8492.8,1301.97 ; 5603.36,61.71 5603.36,1426 ; 5935.06,61.71 5935.06,1426 ; 6570.91,61.71 6570.91,1426 ; 6829.71,61.71 6829.71,1426 ; 7204.46,61.71 7204.46,1426 ; 7927,61.71 7927,1426 ; 5266,61.71 8492.8,61.71 8492.8,1426 5266,1426 5266,61.71
  text "Symbol" at 5340.42,1339.18 h72
  text "Quantity" at 5640.57,1339.18 h72
  text "Finished Hole Size" at 5972.26,1339.18 h72
  text "Plated" at 6608.12,1339.18 h72
  text "Hole Type" at 6866.92,1339.18 h72
  text "Drill Layer Pair" at 7241.67,1339.18 h72
  text "Hole Tolerance" at 7964.21,1339.18 h72
  text "13" at 5640.57,1215.15 h60
  text "7.87mil (0.200mm)" at 5972.26,1215.15 h60
  text "PTH" at 6608.12,1215.15 h60
  text "Round" at 6866.92,1215.15 h60
  text "Top Layer - Bottom Layer" at 7241.67,1215.15 h60
  text "97" at 5640.57,1091.13 h60
  text "10.00mil (0.254mm)" at 5972.26,1091.13 h60
  text "PTH" at 6608.12,1091.13 h60
  text "Round" at 6866.92,1091.13 h60
  text "Top Layer - Bottom Layer" at 7241.67,1091.13 h60
  text "127" at 5640.57,967.1 h60
  text "16.00mil (0.406mm)" at 5972.26,967.1 h60
  text "PTH" at 6608.12,967.1 h60
  text "Round" at 6866.92,967.1 h60
  text "Top Layer - Bottom Layer" at 7241.67,967.1 h60
  text "8" at 5640.57,843.07 h60
  text "33.47mil (0.850mm)" at 5972.26,843.07 h60
  text "PTH" at 6608.12,843.07 h60
  text "Round" at 6866.92,843.07 h60
  text "Top Layer - Bottom Layer" at 7241.67,843.07 h60
  text "16" at 5640.57,719.05 h60
  text "35.04mil (0.890mm)" at 5972.26,719.05 h60
  text "PTH" at 6608.12,719.05 h60
  text "Round" at 6866.92,719.05 h60
  text "Top Layer - Bottom Layer" at 7241.67,719.05 h60
  text "12" at 5640.57,595.02 h60
  text "40.00mil (1.016mm)" at 5972.26,595.02 h60
  text "PTH" at 6608.12,595.02 h60
  text "Round" at 6866.92,595.02 h60
  text "Top Layer - Bottom Layer" at 7241.67,595.02 h60
  text "4" at 5640.57,470.99 h60
  text "50.00mil (1.270mm)" at 5972.26,470.99 h60
  text "PTH" at 6608.12,470.99 h60
  text "Round" at 6866.92,470.99 h60
  text "Top Layer - Bottom Layer" at 7241.67,470.99 h60
  text "4" at 5640.57,346.97 h60
  text "61.81mil (1.570mm)" at 5972.26,346.97 h60
  text "PTH" at 6608.12,346.97 h60
  text "Round" at 6866.92,346.97 h60
  text "Top Layer - Bottom Layer" at 7241.67,346.97 h60
  text "4" at 5640.57,222.94 h60
  text "128.00mil (3.251mm)" at 5972.26,222.94 h60
  text "PTH" at 6608.12,222.94 h60
  text "Round" at 6866.92,222.94 h60
  text "Top Layer - Bottom Layer" at 7241.67,222.94 h60
  text "285 Total" at 5640.57,98.91 h60
  text ".Layer_Name" at 577,-858.49 h60
M17 Embedded Cavity:
  text ".Layer_Name" at 577,-858.49 h60
M18 Embedded Assembly:
  text ".Layer_Name" at 577,-858.49 h60
M19 Embedded Keepout:
  text ".Layer_Name" at 577,-858.49 h60

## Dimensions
0,-400 to 1000,-400 on M2 Board Dimensions
0,0 to 0,3000 on M2 Board Dimensions
0,0 to 5000,0 on M2 Board Dimensions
